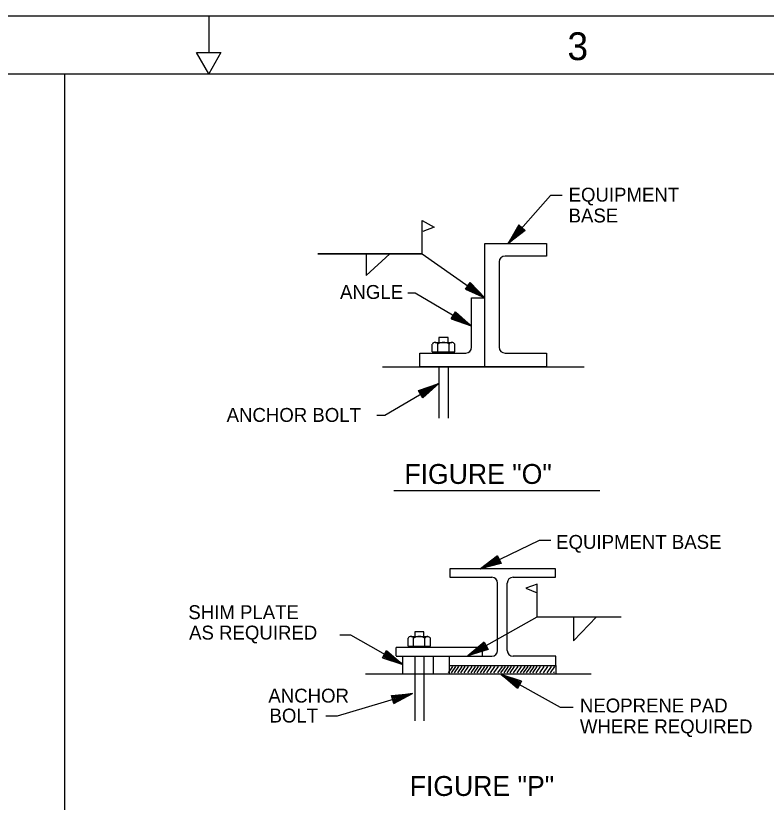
# Model space of a CAD drawing. Extents: x 10040.55 to 10045.84, y 10033.26 to 10035.76.
# Drawn here: x 10042.2 to 10042.739, y 10035.19 to 10035.756 of the extents above; entities that cross this region are included whole.
import ezdxf

# ---------------------------------------------------------------- set-up
doc = ezdxf.new("R2010")
doc.units = 0
doc.layers.add('Level 1', color=7, linetype='Continuous')
doc.layers.add('Level 2', color=7, linetype='Continuous')

msp = doc.modelspace()

# ---------------------------------------------------------------- linework, layer by layer
at = {"layer": 'Level 1'}
for p, q in [((10040.54697, 10035.75552), (10044.04697, 10035.75552)), ((10042.33864, 10035.75552), (10042.33864, 10035.7291)), ((10042.32972, 10035.7291), (10042.3473, 10035.7291)), ((10042.33864, 10035.71385), (10042.32972, 10035.7291)), ((10042.3473, 10035.7291), (10042.33864, 10035.71385)), ((10040.71364, 10035.71385), (10044.0053, 10035.71385))]:
    msp.add_line(p, q, dxfattribs=at)
at = {"layer": 'Level 2'}
for p, q in [((10042.2348, 10035.71385), (10042.2348, 10033.29719)), ((10042.4921, 10035.58425), (10042.4921, 10035.60832)), ((10042.4921, 10035.60832), (10042.50063, 10035.60358)), ((10042.50063, 10035.60358), (10042.49258, 10035.60027)), ((10042.56163, 10035.60507), (10042.55394, 10035.59179)), ((10042.56163, 10035.60507), (10042.55394, 10035.59179)), ((10042.55394, 10035.59179), (10042.56221, 10035.60457)), ((10042.55394, 10035.59179), (10042.56221, 10035.60457)), ((10042.55394, 10035.59179), (10042.56285, 10035.60403)), ((10042.55394, 10035.59179), (10042.56285, 10035.60403)), ((10042.55394, 10035.59179), (10042.56334, 10035.60357)), ((10042.55394, 10035.59179), (10042.56334, 10035.60357)), ((10042.56388, 10035.60311), (10042.55394, 10035.59179)), ((10042.56388, 10035.60311), (10042.55394, 10035.59179)), ((10042.55394, 10035.59179), (10042.56444, 10035.6026)), ((10042.55394, 10035.59179), (10042.56444, 10035.6026)), ((10042.55394, 10035.59179), (10042.565, 10035.60213)), ((10042.55394, 10035.59179), (10042.565, 10035.60213)), ((10042.55394, 10035.59179), (10042.56554, 10035.60164)), ((10042.55394, 10035.59179), (10042.56554, 10035.60164)), ((10042.56615, 10035.60109), (10042.55394, 10035.59179)), ((10042.56615, 10035.60109), (10042.55394, 10035.59179)), ((10042.56163, 10035.60507), (10042.56615, 10035.60109)), ((10042.56163, 10035.60507), (10042.56615, 10035.60109)), ((10042.53713, 10035.50304), (10042.53713, 10035.59184)), ((10042.53713, 10035.59184), (10042.58153, 10035.59184)), ((10042.58153, 10035.59184), (10042.58153, 10035.58273)), ((10042.4921, 10035.58425), (10042.41709, 10035.58425)), ((10042.45183, 10035.58425), (10042.45183, 10035.56885)), ((10042.45183, 10035.56885), (10042.46881, 10035.58425)), ((10042.4921, 10035.58425), (10042.4921, 10035.58425)), ((10042.54743, 10035.57856), (10042.54743, 10035.51711)), ((10042.58153, 10035.58273), (10042.55159, 10035.58273)), ((10042.52308, 10035.5588), (10042.52656, 10035.56372)), ((10042.52479, 10035.56124), (10042.53713, 10035.55259)), ((10042.53713, 10035.55259), (10042.52523, 10035.56185)), ((10042.53713, 10035.55259), (10042.52566, 10035.56247)), ((10042.53713, 10035.55259), (10042.52607, 10035.56305)), ((10042.52656, 10035.56372), (10042.53713, 10035.55259)), ((10042.52308, 10035.5588), (10042.53713, 10035.55259)), ((10042.53713, 10035.55259), (10042.52352, 10035.55943)), ((10042.53713, 10035.55259), (10042.52399, 10035.56013)), ((10042.53713, 10035.55259), (10042.5244, 10035.56066)), ((10042.5276, 10035.51711), (10042.5276, 10035.55259)), ((10042.5276, 10035.55259), (10042.53713, 10035.55259)), ((10042.51289, 10035.53751), (10042.51595, 10035.5427)), ((10042.52738, 10035.53245), (10042.51368, 10035.53891)), ((10042.52738, 10035.53245), (10042.51404, 10035.53947)), ((10042.51439, 10035.54008), (10042.52738, 10035.53245)), ((10042.52738, 10035.53245), (10042.51478, 10035.54073)), ((10042.52738, 10035.53245), (10042.51515, 10035.54138)), ((10042.52738, 10035.53245), (10042.51553, 10035.54199)), ((10042.51595, 10035.5427), (10042.52738, 10035.53245)), ((10042.51289, 10035.53751), (10042.52738, 10035.53245)), ((10042.52738, 10035.53245), (10042.51327, 10035.53817)), ((10042.49932, 10035.51383), (10042.49932, 10035.51945)), ((10042.50135, 10035.52067), (10042.51342, 10035.52067)), ((10042.50332, 10035.51383), (10042.50332, 10035.51945)), ((10042.51142, 10035.51383), (10042.51142, 10035.51945)), ((10042.51544, 10035.51383), (10042.51544, 10035.5194)), ((10042.49034, 10035.50304), (10042.49034, 10035.51295)), ((10042.49034, 10035.51295), (10042.52344, 10035.51295)), ((10042.49932, 10035.51383), (10042.51544, 10035.51383)), ((10042.55159, 10035.51295), (10042.58153, 10035.51295)), ((10042.58153, 10035.51295), (10042.58153, 10035.50304)), ((10042.46352, 10035.50304), (10042.60849, 10035.50304)), ((10042.58153, 10035.50304), (10042.49034, 10035.50304)), ((10042.50408, 10035.50304), (10042.50408, 10035.46607)), ((10042.5107, 10035.50304), (10042.5107, 10035.46607)), ((10042.48941, 10035.48601), (10042.50391, 10035.49104)), ((10042.50391, 10035.49104), (10042.48981, 10035.4853)), ((10042.50391, 10035.49104), (10042.49018, 10035.48467)), ((10042.50391, 10035.49104), (10042.49056, 10035.48403)), ((10042.49094, 10035.48338), (10042.50391, 10035.49104)), ((10042.50391, 10035.49104), (10042.4913, 10035.48277)), ((10042.50391, 10035.49104), (10042.49163, 10035.48219)), ((10042.50391, 10035.49104), (10042.49207, 10035.48147)), ((10042.49246, 10035.48081), (10042.50391, 10035.49104)), ((10042.49246, 10035.48081), (10042.48941, 10035.48601)), ((10042.47154, 10035.41414), (10042.61977, 10035.41414)), ((10042.54622, 10035.36708), (10042.53394, 10035.35788)), ((10042.53394, 10035.35788), (10042.54655, 10035.3664)), ((10042.53394, 10035.35788), (10042.54694, 10035.36565)), ((10042.53394, 10035.35788), (10042.5472, 10035.36503)), ((10042.54752, 10035.36441), (10042.53394, 10035.35788)), ((10042.53394, 10035.35788), (10042.54783, 10035.36372)), ((10042.54622, 10035.36708), (10042.54881, 10035.36165)), ((10042.58799, 10035.3577), (10042.51188, 10035.3577)), ((10042.51188, 10035.3577), (10042.51188, 10035.35174)), ((10042.53394, 10035.35788), (10042.54817, 10035.36305)), ((10042.53394, 10035.35788), (10042.54847, 10035.3624)), ((10042.54881, 10035.36165), (10042.53394, 10035.35788)), ((10042.58799, 10035.35174), (10042.58799, 10035.3577)), ((10042.51188, 10035.35174), (10042.54208, 10035.35174)), ((10042.54625, 10035.29907), (10042.54625, 10035.34757)), ((10042.55319, 10035.29907), (10042.55319, 10035.34757)), ((10042.55735, 10035.35174), (10042.58799, 10035.35174)), ((10042.57469, 10035.34683), (10042.56659, 10035.34389)), ((10042.57469, 10035.32328), (10042.57469, 10035.34683)), ((10042.56659, 10035.34389), (10042.57469, 10035.34057)), ((10042.52485, 10035.29514), (10042.57469, 10035.32328)), ((10042.57469, 10035.32328), (10042.63503, 10035.32328)), ((10042.60081, 10035.32328), (10042.60081, 10035.30599)), ((10042.60081, 10035.30599), (10042.61736, 10035.32328)), ((10042.4819, 10035.30231), (10042.4819, 10035.30793)), ((10042.48393, 10035.30915), (10042.49599, 10035.30915)), ((10042.4859, 10035.30231), (10042.4859, 10035.30793)), ((10042.49399, 10035.30231), (10042.49399, 10035.30793)), ((10042.49801, 10035.30231), (10042.49801, 10035.30788)), ((10042.5355, 10035.30125), (10042.47342, 10035.30125)), ((10042.47342, 10035.29517), (10042.47342, 10035.30125)), ((10042.4819, 10035.30231), (10042.49801, 10035.30231)), ((10042.53649, 10035.30516), (10042.52485, 10035.29514)), ((10042.52485, 10035.29514), (10042.53686, 10035.30449)), ((10042.52485, 10035.29514), (10042.53729, 10035.30376)), ((10042.52485, 10035.29514), (10042.5376, 10035.30317)), ((10042.53796, 10035.30256), (10042.52485, 10035.29514)), ((10042.52485, 10035.29514), (10042.53832, 10035.3019)), ((10042.52485, 10035.29514), (10042.5387, 10035.30126)), ((10042.5355, 10035.29517), (10042.5355, 10035.30125)), ((10042.53649, 10035.30516), (10042.53944, 10035.2999)), ((10042.46349, 10035.29378), (10042.46649, 10035.29901)), ((10042.47805, 10035.28892), (10042.46463, 10035.29576)), ((10042.46496, 10035.29638), (10042.47805, 10035.28892)), ((10042.47805, 10035.28892), (10042.46534, 10035.29702)), ((10042.47805, 10035.28892), (10042.46571, 10035.29768)), ((10042.47805, 10035.28892), (10042.46607, 10035.2983)), ((10042.46649, 10035.29901), (10042.47805, 10035.28892)), ((10042.52485, 10035.29514), (10042.53904, 10035.30063)), ((10042.53944, 10035.2999), (10042.52485, 10035.29514)), ((10042.46349, 10035.29378), (10042.47805, 10035.28892)), ((10042.47805, 10035.28892), (10042.46388, 10035.29445)), ((10042.47805, 10035.28892), (10042.46427, 10035.29519)), ((10042.47342, 10035.29491), (10042.54208, 10035.29491)), ((10042.47803, 10035.28232), (10042.47803, 10035.29491)), ((10042.48666, 10035.29491), (10042.48666, 10035.2485)), ((10042.49327, 10035.29491), (10042.49327, 10035.2485)), ((10042.50018, 10035.28232), (10042.50018, 10035.29491)), ((10042.51179, 10035.28822), (10042.51179, 10035.29491)), ((10042.58805, 10035.29491), (10042.55735, 10035.29491)), ((10042.58805, 10035.28822), (10042.58805, 10035.29491)), ((10042.51097, 10035.28301), (10042.51414, 10035.28763)), ((10042.51179, 10035.28232), (10042.51179, 10035.28822)), ((10042.51179, 10035.28822), (10042.58805, 10035.28822)), ((10042.51263, 10035.28542), (10042.51414, 10035.28763)), ((10042.51313, 10035.28301), (10042.51629, 10035.28763)), ((10042.51313, 10035.28301), (10042.51629, 10035.28763)), ((10042.51529, 10035.28301), (10042.51846, 10035.28763)), ((10042.51529, 10035.28301), (10042.51846, 10035.28763)), ((10042.51759, 10035.28301), (10042.52076, 10035.28763)), ((10042.51759, 10035.28301), (10042.52076, 10035.28763)), ((10042.51975, 10035.28301), (10042.52292, 10035.28763)), ((10042.51975, 10035.28301), (10042.52292, 10035.28763)), ((10042.5222, 10035.28301), (10042.52536, 10035.28763)), ((10042.5222, 10035.28301), (10042.52536, 10035.28763)), ((10042.52479, 10035.28301), (10042.52796, 10035.28763)), ((10042.52479, 10035.28301), (10042.52796, 10035.28763)), ((10042.52725, 10035.28301), (10042.53042, 10035.28763)), ((10042.52941, 10035.28301), (10042.53257, 10035.28763)), ((10042.53157, 10035.28301), (10042.53474, 10035.28763)), ((10042.53388, 10035.28301), (10042.53704, 10035.28763)), ((10042.53603, 10035.28301), (10042.5392, 10035.28763)), ((10042.53848, 10035.28301), (10042.54165, 10035.28763)), ((10042.54107, 10035.28301), (10042.54424, 10035.28763)), ((10042.54367, 10035.28301), (10042.54683, 10035.28763)), ((10042.54655, 10035.28301), (10042.54972, 10035.28763)), ((10042.54871, 10035.28301), (10042.55188, 10035.28763)), ((10042.55088, 10035.28301), (10042.55404, 10035.28763)), ((10042.55318, 10035.28301), (10042.55634, 10035.28763)), ((10042.55533, 10035.28301), (10042.5585, 10035.28763)), ((10042.55778, 10035.28301), (10042.56095, 10035.28763)), ((10042.56038, 10035.28301), (10042.56354, 10035.28763)), ((10042.56283, 10035.28301), (10042.566, 10035.28763)), ((10042.56499, 10035.28301), (10042.56816, 10035.28763)), ((10042.56716, 10035.28301), (10042.57032, 10035.28763)), ((10042.56946, 10035.28301), (10042.57263, 10035.28763)), ((10042.57161, 10035.28301), (10042.57478, 10035.28763)), ((10042.57406, 10035.28301), (10042.57723, 10035.28763)), ((10042.57666, 10035.28301), (10042.57982, 10035.28763)), ((10042.57925, 10035.28301), (10042.58242, 10035.28763)), ((10042.58184, 10035.28301), (10042.58501, 10035.28763)), ((10042.58429, 10035.28301), (10042.58746, 10035.28763)), ((10042.58659, 10035.28301), (10042.58725, 10035.28396)), ((10042.58805, 10035.28822), (10042.58805, 10035.28232)), ((10042.45126, 10035.28232), (10042.6136, 10035.28232)), ((10042.56198, 10035.27449), (10042.5488, 10035.28178)), ((10042.56049, 10035.27183), (10042.5488, 10035.28178)), ((10042.56342, 10035.27709), (10042.5488, 10035.28178)), ((10042.5488, 10035.28178), (10042.56125, 10035.27318)), ((10042.5488, 10035.28178), (10042.56266, 10035.27568)), ((10042.5488, 10035.28178), (10042.5609, 10035.27254)), ((10042.5488, 10035.28178), (10042.5616, 10035.27383)), ((10042.5488, 10035.28178), (10042.56231, 10035.2751)), ((10042.5488, 10035.28178), (10042.56305, 10035.27643)), ((10042.56342, 10035.27709), (10042.56049, 10035.27183)), ((10042.46991, 10035.26673), (10042.48519, 10035.26811)), ((10042.48519, 10035.26811), (10042.47013, 10035.26595)), ((10042.48519, 10035.26811), (10042.47032, 10035.26525)), ((10042.48519, 10035.26811), (10042.47054, 10035.26453)), ((10042.47075, 10035.26381), (10042.48519, 10035.26811)), ((10042.48519, 10035.26811), (10042.47096, 10035.26314)), ((10042.48519, 10035.26811), (10042.47113, 10035.26249)), ((10042.48519, 10035.26811), (10042.47139, 10035.26169)), ((10042.4716, 10035.26096), (10042.48519, 10035.26811)), ((10042.4716, 10035.26096), (10042.46991, 10035.26673))]:
    msp.add_line(p, q, dxfattribs=at)
for points in [[(10042.59258, 10035.6263), (10042.5843, 10035.6263), (10042.55394, 10035.59179)], [(10042.41709, 10035.58425), (10042.4921, 10035.58425), (10042.53713, 10035.55259)], [(10042.48182, 10035.55626), (10042.487, 10035.55626), (10042.52738, 10035.53245)], [(10042.5107, 10035.5207), (10042.5107, 10035.52408), (10042.50408, 10035.52408), (10042.50408, 10035.5207)], [(10042.4594, 10035.46827), (10042.46526, 10035.46827), (10042.50391, 10035.49104)], [(10042.58447, 10035.37809), (10042.57615, 10035.37809), (10042.53394, 10035.35788)], [(10042.49327, 10035.30918), (10042.49327, 10035.31256), (10042.48666, 10035.31256), (10042.48666, 10035.30918)], [(10042.43288, 10035.31032), (10042.4406, 10035.31032), (10042.47805, 10035.28892)], [(10042.60052, 10035.25801), (10042.5916, 10035.25801), (10042.5488, 10035.28178)], [(10042.42277, 10035.25206), (10042.43109, 10035.25206), (10042.48519, 10035.26811)]]:
    msp.add_lwpolyline(points, dxfattribs=at)
for centre, radius, start, end in [((10042.55159, 10035.57856), 0.00417, 90, 180), ((10042.50133, 10035.51841), 0.00225, 27.8877, 152.0342), ((10042.50737, 10035.51322), 0.00744, 57.0062, 122.943), ((10042.51341, 10035.51839), 0.00225, 26.7827, 151.8391), ((10042.52344, 10035.51711), 0.00417, 270, 0), ((10042.55159, 10035.51711), 0.00417, 180, 270), ((10042.54208, 10035.34757), 0.00417, 0, 90), ((10042.55735, 10035.34757), 0.00417, 90, 180), ((10042.4839, 10035.30689), 0.00225, 27.8877, 152.0342), ((10042.48994, 10035.3017), 0.00744, 57.0062, 122.943), ((10042.49598, 10035.30687), 0.00225, 26.7827, 151.8391), ((10042.54208, 10035.29907), 0.00417, 270, 0), ((10042.55735, 10035.29907), 0.00417, 180, 270)]:
    msp.add_arc(centre, radius, start, end, dxfattribs=at)

# ---------------------------------------------------------------- texts
at = {"layer": 'Level 1'}
msp.add_text('3', height=0.02, dxfattribs=at).set_placement((10042.59647, 10035.7236))
at = {"layer": 'Level 2'}
for s, height, p in [('EQUIPMENT', 0.01, (10042.59731, 10035.62185)), ('BASE', 0.01, (10042.59731, 10035.60685)), ('ANGLE', 0.01, (10042.43297, 10035.55188)), ('ANCHOR BOLT', 0.01, (10042.35143, 10035.46347)), ('FIGURE "O"', 0.014301, (10042.47923, 10035.41888)), ('EQUIPMENT BASE', 0.01, (10042.58836, 10035.37215)), ('SHIM PLATE', 0.01, (10042.32391, 10035.32164)), ('AS REQUIRED', 0.01, (10042.32445, 10035.30696)), ('ANCHOR', 0.01, (10042.38144, 10035.26163)), ('NEOPRENE PAD', 0.01, (10042.60545, 10035.25454)), ('BOLT  ', 0.01, (10042.38227, 10035.24731)), ('WHERE REQUIRED', 0.01, (10042.60545, 10035.23954)), ('FIGURE "P"', 0.014301, (10042.48306, 10035.19452))]:
    msp.add_text(s, height=height, dxfattribs=at).set_placement(p)

doc.saveas('drawing.dxf')
